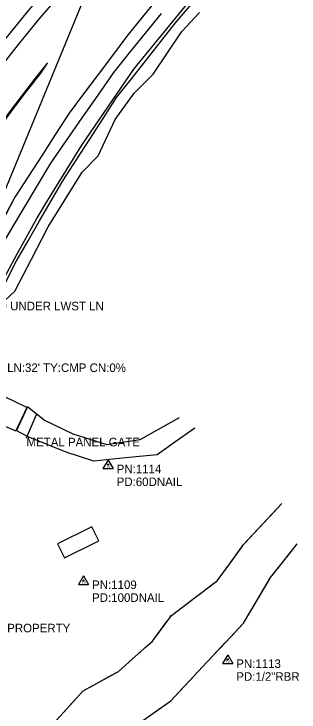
# Model space of a CAD drawing. Extents: x 1282810 to 1284464, y 402460 to 405899.
# Drawn here: x 1283634 to 1283800.2, y 404059.6 to 404466.8 of the extents above; entities that cross this region are included whole.
import ezdxf

# ---------------------------------------------------------------- set-up
doc = ezdxf.new("R2010")
doc.units = 0
for name, color, linetype in [('MOT_Proposed Road_Stage 2', 7, 'Continuous'), ('MOT_Shld_Stage 2', 7, 'Continuous'), ('S_BASELINE', 7, 'Continuous'), ('S_CROSS_DRAIN_ANNOT', 7, 'Continuous'), ('S_DITCHLINE', 7, 'Continuous'), ('S_EDGE_CONCRETE', 7, 'Continuous'), ('S_EDGE_PAVEMENT', 7, 'Continuous'), ('S_GATE', 7, 'Continuous'), ('S_GATE_ANNOT', 7, 'Continuous'), ('S_GRAVEL_ROAD', 7, 'Continuous'), ('S_MSC_PT_SYM', 7, 'Continuous'), ('S_SECONDARY_CTL', 7, 'Continuous'), ('S_SECONDARY_CTL_ANNOT', 7, 'Continuous'), ('S_SHOULDER', 7, 'Continuous'), ('S_STREAM', 7, 'Continuous'), ('S_SURVEY_TEXT_ANNOT', 7, 'Continuous')]:
    doc.layers.add(name, color=color, linetype=linetype)

msp = doc.modelspace()

# ---------------------------------------------------------------- linework, layer by layer
at = {"layer": 'MOT_Proposed Road_Stage 2'}
for points in [[(1283718.07, 404476.36), (1283708.96, 404465.16), (1283699.85, 404453.97), (1283691.43, 404442.7), (1283683.01, 404431.44), (1283674.6, 404420.17), (1283666.18, 404408.91), (1283658.24, 404396.65), (1283650.31, 404384.4), (1283642.37, 404372.14), (1283634.44, 404359.89), (1283623.48, 404339.36)], [(1283718.07, 404476.36), (1283708.96, 404465.16), (1283699.85, 404453.97), (1283691.43, 404442.7), (1283683.01, 404431.44), (1283675.48, 404421.36)]]:
    msp.add_lwpolyline(points, dxfattribs=at)
for centre, radius, start, end in [((1284344.24, 403884.33), 905.47, 138.45801, 157.33333), ((1284344.24, 403884.33), 885.47, 141.27466, 147.66939), ((1284466.96, 403888.72), 981.75, 145.96042, 146.49278)]:
    msp.add_arc(centre, radius, start, end, dxfattribs=at)
at = {"layer": 'MOT_Shld_Stage 2'}
msp.add_arc((1284344.24, 403884.33), 913.47, 136.3373, 157.33333, dxfattribs=at)
at = {"layer": 'S_BASELINE'}
msp.add_line((1283396.79, 403800.11), (1283700.58, 404538.68), dxfattribs=at)
at = {"layer": 'S_DITCHLINE'}
for points in [[(1283609.36, 404263.21), (1283609.41, 404264.74), (1283614.77, 404282.66), (1283625.07, 404302.72), (1283635.38, 404322.78), (1283642.15, 404334.45), (1283648.92, 404346.13), (1283655.69, 404357.8), (1283662.46, 404369.47), (1283670.31, 404381.63), (1283678.16, 404393.78), (1283686, 404405.93), (1283693.85, 404418.09), (1283702.42, 404428.99), (1283710.99, 404439.89), (1283719.56, 404450.8), (1283728.14, 404461.7), (1283737.59, 404472.54)], [(1283610.29, 404262.6), (1283611.47, 404263.21), (1283614.97, 404271.12), (1283617.46, 404271.95), (1283620.45, 404279.13), (1283622.59, 404283.42), (1283628.37, 404299.55), (1283634.55, 404305.06), (1283644.21, 404323.84), (1283653.88, 404342.62), (1283663.81, 404358.58), (1283673.75, 404374.54), (1283683.07, 404383.99), (1283693.03, 404405.26), (1283703.98, 404420.61), (1283715.07, 404431.72), (1283723.5, 404444.12), (1283731.94, 404456.53), (1283742.27, 404467.67)]]:
    msp.add_lwpolyline(points, dxfattribs=at)
at = {"layer": 'S_EDGE_CONCRETE'}
msp.add_lwpolyline([(1283618.25, 404270.79), (1283615.62, 404264.61), (1283614.91, 404262.89), (1283613.43, 404259.58), (1283608.69, 404261.34), (1283603.27, 404264.04), (1283613.73, 404284.79), (1283624.19, 404305.55), (1283635.7, 404326.58), (1283647.2, 404347.61), (1283653.8, 404358.29), (1283660.4, 404368.97), (1283667, 404379.65), (1283673.6, 404390.33), (1283681.18, 404401.41), (1283688.76, 404412.48), (1283696.34, 404423.56), (1283703.92, 404434.64), (1283719.6, 404453.87), (1283735.28, 404473.1)], dxfattribs=at)
msp.add_lwpolyline([(1283683.44, 404159.43), (1283679.46, 404167.57), (1283659.43, 404157.78), (1283663.51, 404149.53)], close=True, dxfattribs=at)
at = {"layer": 'S_EDGE_PAVEMENT'}
for points in [[(1283718.07, 404476.36), (1283708.96, 404465.16), (1283699.85, 404453.97), (1283691.43, 404442.7), (1283683.01, 404431.44), (1283674.6, 404420.17), (1283666.18, 404408.91), (1283658.24, 404396.65), (1283650.31, 404384.4), (1283642.37, 404372.14), (1283634.44, 404359.89), (1283627.09, 404346.13)], [(1283603.85, 404368.64), (1283606.42, 404372.59), (1283609.17, 404376.76), (1283611.96, 404380.9), (1283614.76, 404385.04), (1283617.6, 404389.15), (1283620.47, 404393.24), (1283623.35, 404397.32), (1283626.24, 404401.4), (1283629.16, 404405.45), (1283632.11, 404409.48), (1283635.09, 404413.5), (1283638.09, 404417.49), (1283641.14, 404421.45), (1283644.2, 404425.39), (1283647.29, 404429.32), (1283648.41, 404430.76)], [(1283593.24, 404267.8), (1283595.7, 404261.72), (1283599.33, 404258.06), (1283610.19, 404252.56), (1283628.07, 404243.86), (1283641.66, 404237.19), (1283635.3, 404223.5), (1283614.86, 404231.99), (1283600.63, 404239.28), (1283592.76, 404242.6), (1283586.77, 404243.11), (1283580.86, 404240.13)]]:
    msp.add_lwpolyline(points, dxfattribs=at)
at = {"layer": 'S_GATE'}
msp.add_line((1283641.3, 404219.58), (1283647.04, 404233.15), dxfattribs=at)
at = {"layer": 'S_GRAVEL_ROAD'}
msp.add_lwpolyline([(1283739.42, 404225.21), (1283728.47, 404217.48), (1283717.52, 404209.75), (1283699.07, 404207.85), (1283680.62, 404205.94), (1283664.43, 404211.18), (1283642.19, 404220.25), (1283635.33, 404223.9), (1283641.78, 404237.76), (1283651.78, 404229.96), (1283668.36, 404221.97), (1283688.07, 404215.67), (1283707.65, 404218.62), (1283719.05, 404225.04), (1283730.45, 404231.46)], dxfattribs=at)
at = {"layer": 'S_MSC_PT_SYM'}
for points in [[(1283647.04, 404233.15), (1283647.04, 404233.2), (1283647.04, 404233.15), (1283646.99, 404233.15), (1283647.04, 404233.15), (1283647.04, 404233.1), (1283647.04, 404233.15), (1283647.09, 404233.15)], [(1283641.3, 404219.58), (1283641.3, 404219.63), (1283641.3, 404219.58), (1283641.25, 404219.58), (1283641.3, 404219.58), (1283641.3, 404219.53), (1283641.3, 404219.58), (1283641.35, 404219.58)]]:
    msp.add_lwpolyline(points, dxfattribs=at)
at = {"layer": 'S_SECONDARY_CTL'}
for p, q in [((1283688.89, 404206.54), (1283685.88, 404201.59)), ((1283688.89, 404206.54), (1283691.84, 404201.59)), ((1283685.88, 404201.59), (1283691.84, 404201.59)), ((1283674.55, 404138.98), (1283671.54, 404134.03)), ((1283674.55, 404138.98), (1283677.5, 404134.03)), ((1283671.54, 404134.03), (1283677.5, 404134.03)), ((1283758.62, 404092.94), (1283755.61, 404087.98)), ((1283758.62, 404092.94), (1283761.57, 404087.98)), ((1283755.61, 404087.98), (1283761.57, 404087.98))]:
    msp.add_line(p, q, dxfattribs=at)
for centre, radius in [((1283688.89, 404203.93), 0.311), ((1283688.89, 404203.93), 0.183), ((1283688.89, 404203.93), 0.103), ((1283674.55, 404136.37), 0.311), ((1283674.55, 404136.37), 0.183), ((1283674.55, 404136.37), 0.103), ((1283758.62, 404090.33), 0.311), ((1283758.62, 404090.33), 0.183), ((1283758.62, 404090.33), 0.103)]:
    msp.add_circle(centre, radius, dxfattribs=at)
at = {"layer": 'S_SHOULDER'}
for points in [[(1283594.98, 404271.8), (1283602.33, 404285.78), (1283609.68, 404299.75), (1283617.03, 404313.73), (1283624.38, 404327.7), (1283632.14, 404340.73), (1283639.89, 404353.76), (1283647.64, 404366.78), (1283655.39, 404379.81), (1283664.59, 404393.03), (1283673.79, 404406.25), (1283682.99, 404419.46), (1283692.19, 404432.68), (1283701.44, 404444.15), (1283710.69, 404455.61), (1283719.93, 404467.08)], [(1283632.11, 404409.48), (1283635.09, 404413.5), (1283638.09, 404417.49), (1283641.14, 404421.45), (1283644.2, 404425.39), (1283648.36, 404430.68)]]:
    msp.add_lwpolyline(points, dxfattribs=at)
at = {"layer": 'S_STREAM'}
for points in [[(1283658.67, 404054.79), (1283674.36, 404072.03), (1283694.97, 404083.35), (1283704.84, 404092.19), (1283714.71, 404101.02), (1283725.76, 404115.95), (1283739.13, 404126.06), (1283752.5, 404136.18), (1283760.21, 404146.74), (1283767.92, 404157.31), (1283779.02, 404169.25), (1283790.13, 404181.2)], [(1283783.4, 404173.96), (1283790.13, 404181.19)], [(1283780.31, 404170.63), (1283780.79, 404171.16)], [(1283777.62, 404167.74), (1283778.1, 404168.27)], [(1283774.93, 404164.85), (1283775.41, 404165.37)], [(1283766.2, 404154.96), (1283767.92, 404157.31), (1283772.66, 404162.41)], [(1283705.76, 404052.43), (1283725.51, 404066.21), (1283736.11, 404077.54), (1283746.7, 404088.88), (1283757.3, 404100.21), (1283767.89, 404111.55), (1283775.79, 404124.78), (1283783.68, 404138.01), (1283791.46, 404147.91), (1283799.24, 404157.81)], [(1283760.37, 404146.97), (1283766.2, 404154.95)], [(1283793.06, 404149.95), (1283799.23, 404157.8)], [(1283790.22, 404146.33), (1283790.67, 404146.9)], [(1283757.7, 404143.3), (1283758.12, 404143.88)], [(1283787.75, 404143.19), (1283788.2, 404143.76)], [(1283755.37, 404140.11), (1283755.79, 404140.69)], [(1283785.29, 404140.05), (1283785.73, 404140.62)], [(1283742.7, 404128.76), (1283750.57, 404134.72)], [(1283753.04, 404136.92), (1283753.46, 404137.5)], [(1283778.17, 404128.77), (1283783.28, 404137.35)], [(1283734.81, 404122.8), (1283739.13, 404126.06), (1283742.69, 404128.76)], [(1283773.05, 404120.19), (1283775.79, 404124.78), (1283778.16, 404128.76)], [(1283728.04, 404117.68), (1283728.61, 404118.11)], [(1283731.19, 404120.06), (1283731.76, 404120.49)], [(1283725.11, 404115.08), (1283725.53, 404115.65)], [(1283770.69, 404116.24), (1283771.06, 404116.86)], [(1283717.25, 404104.46), (1283723.13, 404112.4)], [(1283766.17, 404109.7), (1283766.66, 404110.23)], [(1283768.64, 404112.81), (1283769.01, 404113.43)], [(1283757.04, 404099.94), (1283757.3, 404100.21), (1283763.86, 404107.24)], [(1283710.53, 404097.28), (1283714.71, 404101.02), (1283717.25, 404104.45)], [(1283750.22, 404092.64), (1283757.04, 404099.94)], [(1283707.14, 404094.25), (1283707.68, 404094.73)], [(1283701.26, 404088.98), (1283701.79, 404089.46)], [(1283704.2, 404091.62), (1283704.73, 404092.09)], [(1283747.08, 404089.28), (1283747.57, 404089.81)], [(1283690.79, 404081.06), (1283694.97, 404083.35), (1283698.77, 404086.76)], [(1283744.35, 404086.36), (1283744.85, 404086.89)], [(1283682.13, 404076.3), (1283690.78, 404081.05)], [(1283741.62, 404083.45), (1283742.12, 404083.97)], [(1283732.5, 404073.69), (1283736.11, 404077.54), (1283739.32, 404080.98)], [(1283678.14, 404074.11), (1283678.77, 404074.45)], [(1283725.68, 404066.38), (1283732.5, 404073.68)], [(1283671.95, 404069.38), (1283672.43, 404069.91)], [(1283674.68, 404072.21), (1283675.31, 404072.55)], [(1283663.06, 404059.61), (1283669.7, 404066.92)], [(1283718.66, 404061.43), (1283719.26, 404061.84)], [(1283721.94, 404063.72), (1283722.53, 404064.13)]]:
    msp.add_lwpolyline(points, dxfattribs=at)

# ---------------------------------------------------------------- texts
at = {"layer": 'S_CROSS_DRAIN_ANNOT'}
msp.add_text('DI:24" LN:32\' TY:CMP CN:0%', height=5, dxfattribs=at).set_placement((1283609.78, 404257.98))
at = {"layer": 'S_GATE_ANNOT'}
msp.add_text('METAL PANEL GATE', height=5, dxfattribs=at).set_placement((1283641.3, 404214.58))
at = {"layer": 'S_SECONDARY_CTL'}
for p in [(1283687.69, 404201.92), (1283673.35, 404134.36), (1283757.41, 404088.31)]:
    msp.add_text('TV', height=1.5, rotation=360, dxfattribs=at).set_placement(p)
at = {"layer": 'S_SECONDARY_CTL_ANNOT'}
for s, p in [('PN:1114', (1283693.89, 404198.93)), ('PD:60DNAIL', (1283693.89, 404191.43)), ('PN:1109', (1283679.55, 404131.37)), ('PD:100DNAIL', (1283679.55, 404123.87)), ('PN:1113', (1283763.62, 404085.33)), ('PD:1/2"RBR', (1283763.62, 404077.83))]:
    msp.add_text(s, height=5, dxfattribs=at).set_placement(p)
at = {"layer": 'S_SURVEY_TEXT_ANNOT'}
for s, p in [('POINT ON RD UNDER LWST LN', (1283586.05, 404293.94)), ('BILL JOHNSTON PROPERTY', (1283575.77, 404106.09))]:
    msp.add_text(s, height=5, dxfattribs=at).set_placement(p)

doc.saveas('drawing.dxf')
